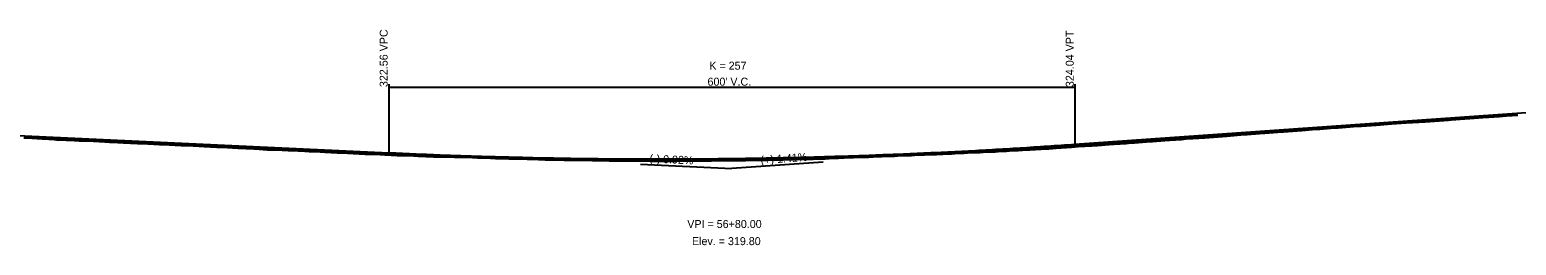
# Model space of a CAD drawing. Extents: x 1876258 to 1926563, y 729739 to 834437.
# Drawn here: x 1883429 to 1884729, y 831536 to 831725 of the extents above; entities that cross this region are included whole.
import ezdxf

# ---------------------------------------------------------------- set-up
doc = ezdxf.new("R2010")
doc.units = 0
for name, color, linetype in [('RD_EX_BldgApp', 7, 'Continuous'), ('RD_EX_H2O_BlueLn', 7, 'Continuous'), ('RD_EX_RailRoad', 7, 'Continuous'), ('RD_HC_Data', 7, 'Continuous'), ('RD_HC_Data_Tic', 7, 'Continuous'), ('RD_HC_TX_Sta50', 7, 'Continuous'), ('RD_PD_ALT5_CL', 7, 'Continuous')]:
    doc.layers.add(name, color=color, linetype=linetype)

msp = doc.modelspace()

# ---------------------------------------------------------------- linework, layer by layer
at = {"layer": 'RD_EX_BldgApp'}
for points in [[(1884669.9, 831645.6), (1884672.1, 831645.8), (1884684, 831646.8), (1884688.6, 831647.1), (1884700, 831647.9), (1884705, 831648.2), (1884714.5, 831648.9), (1884720.5, 831649.3), (1884730.4, 831650)], [(1883999.1, 831609.9), (1884011, 831610), (1884015.3, 831610.1), (1884025.4, 831610.1), (1884029.7, 831610.2), (1884033.7, 831610.2), (1884050.9, 831610.3), (1884055, 831610.4), (1884060.9, 831610.5), (1884069.9, 831610.6), (1884073.6, 831610.7), (1884083.8, 831610.9), (1884088, 831611), (1884097.6, 831611.3), (1884101.9, 831611.4), (1884110.2, 831611.5), (1884114.2, 831611.5), (1884124.7, 831611.8), (1884128.1, 831611.9), (1884136.5, 831612.3), (1884141.2, 831612.6), (1884149.4, 831612.9), (1884154.4, 831613.1), (1884162.5, 831613.3), (1884166.8, 831613.5), (1884171.3, 831613.7), (1884174.3, 831613.9), (1884185.3, 831614.2), (1884188.2, 831614.3), (1884197.3, 831614.7), (1884200.1, 831614.8), (1884202.8, 831614.9), (1884211.6, 831615.3), (1884214.2, 831615.4), (1884222.1, 831615.6), (1884224.9, 831615.7), (1884227.7, 831615.8), (1884235.3, 831616.2), (1884238, 831616.3), (1884243.5, 831616.6), (1884246.1, 831616.7), (1884249.1, 831616.9), (1884260, 831617.4), (1884262.9, 831617.5), (1884270.2, 831617.9), (1884273.3, 831618), (1884278.9, 831618.4), (1884283.4, 831618.6), (1884288.6, 831618.9), (1884291.7, 831619), (1884293.5, 831619.1), (1884301.2, 831619.5), (1884303.7, 831619.6), (1884313.7, 831620.2), (1884320.3, 831620.6), (1884326.6, 831621), (1884340, 831622), (1884346.1, 831622.4), (1884358, 831623.2), (1884362.8, 831623.5), (1884373.1, 831624.3), (1884377.5, 831624.6), (1884388, 831625.3), (1884392.4, 831625.7), (1884395.1, 831625.8), (1884405.6, 831626.6), (1884411, 831627), (1884421.9, 831627.9), (1884426.1, 831628.2), (1884436.3, 831628.8), (1884440.4, 831629.1), (1884446.1, 831629.5), (1884456.6, 831630.2), (1884460.5, 831630.4), (1884472.2, 831631.3), (1884476.1, 831631.7), (1884488.3, 831632.7), (1884493.7, 831633.1), (1884504.6, 831633.9), (1884509.3, 831634.3), (1884520.7, 831635.2), (1884525.4, 831635.5), (1884537.5, 831636.3), (1884541.6, 831636.6), (1884554.2, 831637.6), (1884557.4, 831637.8), (1884566.8, 831638.5), (1884569.8, 831638.8), (1884573.4, 831639), (1884590.2, 831640.2), (1884593.8, 831640.4), (1884606.5, 831641.3), (1884610, 831641.5), (1884613.2, 831641.7), (1884619.9, 831642.3), (1884632.9, 831643.1), (1884638.4, 831643.5), (1884649.5, 831644.1), (1884653.5, 831644.4), (1884665.7, 831645.3), (1884669.9, 831645.6)], [(1883424, 831630.1), (1883431, 831629.8), (1883439.9, 831629.3), (1883445.8, 831629), (1883450.3, 831628.6), (1883452.5, 831628.5), (1883460.9, 831628.2), (1883463.9, 831628), (1883472.4, 831627.6), (1883476.1, 831627.5), (1883484.8, 831627.1), (1883494.6, 831626.6), (1883498.8, 831626.4), (1883506.1, 831626), (1883511, 831625.7), (1883523.2, 831625.2), (1883527.4, 831625.1), (1883542.5, 831624.4), (1883546.6, 831624.2), (1883550.9, 831624), (1883561.5, 831623.5), (1883566.3, 831623.3), (1883577.2, 831622.8), (1883581.7, 831622.6), (1883592.8, 831622), (1883597.3, 831621.9), (1883606.4, 831621.3), (1883611, 831621.1), (1883625.1, 831620.4), (1883629.7, 831620.2), (1883636.7, 831619.7), (1883637.7, 831619.7), (1883640.4, 831619.7), (1883644.3, 831619.5), (1883655, 831619.1), (1883658.1, 831618.9), (1883669.7, 831618.4), (1883673.5, 831618.2), (1883683.1, 831617.8), (1883687.1, 831617.6), (1883697.9, 831617.1), (1883701.8, 831616.9), (1883712, 831616.5), (1883722.4, 831615.9), (1883726.1, 831615.7), (1883735.5, 831615.4), (1883739.6, 831615.2), (1883750.4, 831614.8), (1883754.1, 831614.7), (1883765.1, 831614.3), (1883768.9, 831614.1), (1883782.2, 831613.5), (1883785.3, 831613.4), (1883786.4, 831613.4), (1883800.6, 831613.2), (1883804.1, 831613.2), (1883816.2, 831612.8), (1883820.6, 831612.6), (1883832, 831612.2), (1883836.5, 831612.1), (1883848.1, 831611.8), (1883852.7, 831611.7), (1883864.1, 831611.5), (1883868.2, 831611.4), (1883879.8, 831611), (1883883.8, 831610.9), (1883891.8, 831610.8), (1883896.4, 831610.7), (1883908.6, 831610.5), (1883912.1, 831610.5), (1883921.2, 831610.4), (1883925.4, 831610.3), (1883935.7, 831610.1), (1883940.2, 831610.1), (1883950, 831610.1), (1883954.9, 831610.1), (1883963.2, 831610), (1883972.9, 831609.8), (1883978.9, 831609.7), (1883982.2, 831609.8), (1883993.8, 831609.8), (1883999.1, 831609.9)]]:
    msp.add_lwpolyline(points, dxfattribs=at)
at = {"layer": 'RD_EX_H2O_BlueLn'}
for p, q in [((1883743.1, 831677), (1883743.1, 831617.1)), ((1883743.1, 831674.5), (1884343.1, 831674.5)), ((1884343.1, 831677), (1884343.1, 831624.5))]:
    msp.add_line(p, q, dxfattribs=at)
at = {"layer": 'RD_HC_Data_Tic'}
msp.add_lwpolyline([(1883424.1, 831631.4), (1883431.1, 831631), (1883440, 831630.5), (1883445.9, 831630.2), (1883450.4, 831629.9), (1883452.6, 831629.8), (1883461, 831629.4), (1883464, 831629.2), (1883472.4, 831628.9), (1883476.1, 831628.7), (1883484.9, 831628.3), (1883494.7, 831627.9), (1883498.9, 831627.6), (1883506.2, 831627.2), (1883511.1, 831627), (1883523.2, 831626.5), (1883527.5, 831626.3), (1883542.6, 831625.7), (1883546.7, 831625.4), (1883550.9, 831625.3), (1883561.6, 831624.8), (1883566.3, 831624.5), (1883577.3, 831624), (1883581.8, 831623.8), (1883592.9, 831623.3), (1883597.3, 831623.1), (1883606.5, 831622.6), (1883611, 831622.3), (1883625.1, 831621.7), (1883629.7, 831621.4), (1883636.8, 831621), (1883637.8, 831621), (1883640.5, 831620.9), (1883644.3, 831620.8), (1883655, 831620.3), (1883658.2, 831620.1), (1883669.7, 831619.7), (1883673.6, 831619.5), (1883683.2, 831619), (1883687.2, 831618.8), (1883698, 831618.3), (1883701.8, 831618.2), (1883712.1, 831617.7), (1883722.5, 831617.1), (1883726.1, 831617), (1883735.6, 831616.6), (1883739.6, 831616.4), (1883750.4, 831616), (1883754.2, 831615.9), (1883765.2, 831615.5), (1883769, 831615.3), (1883782.3, 831614.8), (1883785.3, 831614.6), (1883786.4, 831614.6), (1883800.6, 831614.5), (1883804.2, 831614.4), (1883816.3, 831614), (1883820.6, 831613.9), (1883832, 831613.5), (1883836.5, 831613.3), (1883848.1, 831613), (1883852.8, 831613), (1883864.1, 831612.7), (1883868.2, 831612.6), (1883879.8, 831612.2), (1883883.8, 831612.1), (1883891.8, 831612), (1883896.4, 831611.9), (1883908.6, 831611.8), (1883912.1, 831611.7), (1883921.2, 831611.6), (1883925.4, 831611.6), (1883935.8, 831611.4), (1883940.2, 831611.4), (1883950, 831611.4), (1883954.9, 831611.3), (1883963.2, 831611.2), (1883972.9, 831611), (1883978.9, 831611), (1883982.1, 831611), (1883993.8, 831611.1), (1883999.1, 831611.1), (1884011, 831611.3), (1884015.2, 831611.3), (1884025.4, 831611.4), (1884029.6, 831611.4), (1884033.7, 831611.4), (1884050.9, 831611.6), (1884054.9, 831611.6), (1884060.8, 831611.7), (1884069.9, 831611.9), (1884073.5, 831611.9), (1884083.8, 831612.1), (1884088, 831612.2), (1884097.6, 831612.5), (1884101.9, 831612.6), (1884110.2, 831612.7), (1884114.1, 831612.8), (1884124.6, 831613), (1884128.1, 831613.1), (1884136.5, 831613.6), (1884141.2, 831613.8), (1884149.4, 831614.2), (1884154.3, 831614.4), (1884162.4, 831614.6), (1884166.8, 831614.8), (1884171.2, 831615), (1884174.2, 831615.1), (1884185.2, 831615.4), (1884188.1, 831615.5), (1884197.2, 831615.9), (1884200.1, 831616), (1884202.7, 831616.1), (1884211.6, 831616.5), (1884214.2, 831616.6), (1884222.1, 831616.9), (1884224.8, 831616.9), (1884227.6, 831617), (1884235.2, 831617.4), (1884237.9, 831617.5), (1884243.5, 831617.8), (1884246.1, 831617.9), (1884249.1, 831618.1), (1884260, 831618.7), (1884262.8, 831618.8), (1884270.1, 831619.2), (1884273.2, 831619.3), (1884278.8, 831619.6), (1884283.3, 831619.9), (1884288.5, 831620.1), (1884291.7, 831620.2), (1884293.4, 831620.4), (1884301.2, 831620.8), (1884303.6, 831620.9), (1884313.6, 831621.4), (1884320.2, 831621.8), (1884326.5, 831622.2), (1884339.9, 831623.2), (1884346, 831623.6), (1884357.9, 831624.5), (1884362.7, 831624.8), (1884373, 831625.6), (1884377.4, 831625.8), (1884387.9, 831626.5), (1884392.3, 831627), (1884395, 831627.1), (1884405.5, 831627.8), (1884410.9, 831628.3), (1884421.8, 831629.1), (1884426, 831629.4), (1884436.3, 831630.1), (1884440.3, 831630.3), (1884446, 831630.7), (1884456.5, 831631.5), (1884460.4, 831631.7), (1884472.1, 831632.6), (1884475.9, 831632.9), (1884488.2, 831633.9), (1884493.6, 831634.3), (1884504.5, 831635.1), (1884509.2, 831635.5), (1884520.6, 831636.4), (1884525.4, 831636.7), (1884537.4, 831637.6), (1884541.5, 831637.9), (1884554.1, 831638.8), (1884557.3, 831639.1), (1884566.7, 831639.8), (1884569.7, 831640), (1884573.3, 831640.3), (1884590.1, 831641.4), (1884593.7, 831641.7), (1884606.4, 831642.5), (1884609.9, 831642.7), (1884613.1, 831642.9), (1884619.8, 831643.5), (1884632.8, 831644.4), (1884638.3, 831644.8), (1884649.4, 831645.4), (1884653.4, 831645.6), (1884665.6, 831646.5), (1884669.8, 831646.8), (1884672, 831647), (1884683.9, 831648), (1884688.5, 831648.3), (1884699.9, 831649.1), (1884704.9, 831649.4), (1884714.4, 831650.2), (1884720.4, 831650.6), (1884730.3, 831651.2)], dxfattribs=at)
at = {"layer": 'RD_HC_TX_Sta50'}
for p in [(1884122.9, 831608.9), (1883963.2, 831607)]:
    msp.add_line(p, (1884043.1, 831603.3), dxfattribs=at)
at = {"layer": 'RD_PD_ALT5_CL'}
for p, q in [((1884343.1, 831624.5), (1885028.1, 831672.9)), ((1883013.1, 831650.7), (1883743.1, 831617.1))]:
    msp.add_line(p, q, dxfattribs=at)
msp.add_spline([(1883743.1, 831617.1), (1883755.1, 831616.6), (1883767.1, 831616), (1883779.1, 831615.6), (1883791.1, 831615.1), (1883803.1, 831614.7), (1883815.1, 831614.3), (1883827.1, 831613.9), (1883839.1, 831613.6), (1883851.1, 831613.3), (1883863.1, 831613), (1883875.1, 831612.7), (1883887.1, 831612.5), (1883899.1, 831612.3), (1883911.1, 831612.1), (1883923.1, 831612), (1883935.1, 831611.8), (1883947.1, 831611.8), (1883959.1, 831611.7), (1883971.1, 831611.7), (1883983.1, 831611.7), (1883995.1, 831611.7), (1884007.1, 831611.7), (1884019.1, 831611.8), (1884031.1, 831611.9), (1884043.1, 831612), (1884055.1, 831612.2), (1884067.1, 831612.4), (1884079.1, 831612.6), (1884091.1, 831612.9), (1884103.1, 831613.1), (1884115.1, 831613.4), (1884127.1, 831613.8), (1884139.1, 831614.1), (1884151.1, 831614.5), (1884163.1, 831614.9), (1884175.1, 831615.4), (1884187.1, 831615.8), (1884199.1, 831616.3), (1884211.1, 831616.9), (1884223.1, 831617.4), (1884235.1, 831618), (1884247.1, 831618.6), (1884259.1, 831619.2), (1884271.1, 831619.9), (1884283.1, 831620.6), (1884295.1, 831621.3), (1884307.1, 831622.1), (1884319.1, 831622.9), (1884331.1, 831623.7), (1884343.1, 831624.5)], degree=3, dxfattribs=at)

# ---------------------------------------------------------------- texts
at = {"layer": 'RD_EX_H2O_BlueLn'}
for s, p in [('K = 257', (1884023.4, 831689.7)), ("600' V.C.", (1884021.8, 831675.7))]:
    msp.add_text(s, height=7, dxfattribs=at).set_placement(p)
at = {"layer": 'RD_EX_RailRoad'}
for s, p in [('322.56 VPC', (1883742.1, 831674.5)), ('324.04 VPT', (1884342.1, 831674.5))]:
    msp.add_text(s, height=7, rotation=90, dxfattribs=at).set_placement(p)
at = {"layer": 'RD_HC_Data'}
for s, p in [('VPI = 56+80.00', (1884004.1, 831551.3)), ('Elev. = 319.80', (1884008.2, 831536.3))]:
    msp.add_text(s, height=7, dxfattribs=at).set_placement(p)
at = {"layer": 'RD_HC_TX_Sta50'}
for s, rotation, p in [('(-) 0.92%', 357.3675, (1883970.9, 831608.6)), ('(+) 1.41%', 4.041, (1884068.5, 831607.1))]:
    msp.add_text(s, height=7, rotation=rotation, dxfattribs=at).set_placement(p)

doc.saveas('drawing.dxf')
